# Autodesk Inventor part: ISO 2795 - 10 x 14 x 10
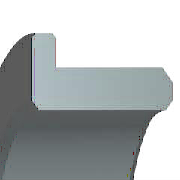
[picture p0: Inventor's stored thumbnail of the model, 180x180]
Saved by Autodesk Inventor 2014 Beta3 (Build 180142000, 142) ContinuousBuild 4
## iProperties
IsCustomPart: 0
Created: 2010-02
Part Number: ISO 2795 - 10 x 14 x 10
Material: Copper Alloy
Description: Plain bearing-Sintered bushes-Dimention and tolerances - Flanged Bearings
Document SubType Name: Modeling
Standard: ISO 2795
Designer: Thom Tremblay
Standard Revision: Fourth edition 1991-11-01
Standards Organization: ISO
Language: en-US
Size Designation: 10 x 14 x 10
Categories: <MemberInstance><Categories><Category DisplayName="Shaft Parts" InternalName="7f7aeb1f-a693-4053-b835-cee3144e0d98" Mnemonic="SHFT"><Category DisplayName="Beari
Density: 7.58 g/cm^3
Appearance: Copper - Satin
Author: Thom Tremblay
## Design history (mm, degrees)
sketch "Sketch"
  geometry: L1 (0, 0)-(10, 0); L2 (0, 0)-(0, 5); L3 (0, 5)-(10, 5); L4 (10, 5)-(10, 7); L5 (10, 7)-(2.6, 7); L6 (0, 9)-(0, 5); L7 (0, 9)-(2, 9); L8 (2, 9)-(2, 7.6); A1 r 0.6 centre (2.6, 7.6) between (2, 7.6) and (2.6, 7); 1 further point
  constraints: 16 end point, 3 parallel, 2 horizontal, 2 perpendicular, 2 point on circle, 2 point on line, 2 tangent, 1 centre point, 1 vertical
  dimensions: "d0" = 10 diameter of L3 L1 (= WD); "d1" = 14 diameter of L5 L1 (= BD); "d2" = 10 distance of L2.end L3.end (= KB); "d14" = 18 diameter of L7 L1 (= KAD1); "d20" = 2 distance of L6.start L7.end (= SD); "d38" = 0.6 radius of A1 (= R)
revolve "Body" sketch "Sketch" stored, may be unused: angle "d3" = 90 deg
body "Solid1"
chamfer "Chamfer1" distance "d8" = 0.4001 (computed from WD, KID2); stored, may be unused: second distance "d9" = 0.4001 (computed from PHH4), angle "d32" = 45 deg
chamfer "Chamfer2" distance "d10" = 0.4001 (computed from KAD2, BD); stored, may be unused: second distance "d11" = 0.4001 (computed from PHH1), angle "d33" = 45 deg
chamfer "Chamfer3" distance "d22" = 0.4001 (computed from PHH5); stored, may be unused: second distance "d23" = 0.4001 (computed from PHH2), angle "d34" = 45 deg
chamfer "Chamfer4" distance "d24" = 0.4001 (computed from PHH5); stored, may be unused: second distance "d25" = 0.4001 (computed from PHH5), angle "d35" = 45 deg
chamfer "Chamfer5" distance "d26" = 0.4001 (computed from WD, KID1); stored, may be unused: second distance "d27" = 0.4001 (computed from PHH3), angle "d36" = 45 deg
other parameters: "WD" = 10 [user parameter; used in 4 equation terms], "BD" = 14 [user parameter; used in 3 equation terms], "KB" = 10 [user parameter; used in 1 equation term], "PHH1" = 0.4 [user parameter; used in 5 equation terms], "KID1" = 10.8 [user parameter; used in 2 equation terms], "KAD1" = 18 [user parameter; used in 1 equation term], "PHH2" = 0.4 (= PHH1) [user parameter; used in 1 equation term], "PHH3" = 0.4 (= PHH1) [user parameter; used in 1 equation term], "PHH4" = 0.4 (= PHH1) [user parameter; used in 1 equation term], "KID2" = 10.8 (= KID1) [user parameter; used in 1 equation term], "KAD2" = 13.2 [user parameter; used in 1 equation term], "SD" = 2 [user parameter; used in 1 equation term], "STI" = 0.2 [user parameter], "SBR" = 2 [user parameter], "PHH5" = 0.4 (= PHH1) [user parameter; used in 3 equation terms], "d28" = 0, "d30" = 0, "d31" = 0, "R" = 0.6 [user parameter; used in 1 equation term], "WR" = 5 (= 0.5 x WD) [user parameter], "BC" = 1000000 [user parameter], "BR" = 7 (= 0.5 x BD) [user parameter], "BBA" = 0 [user parameter], "BC0" = 1000000 [user parameter]
